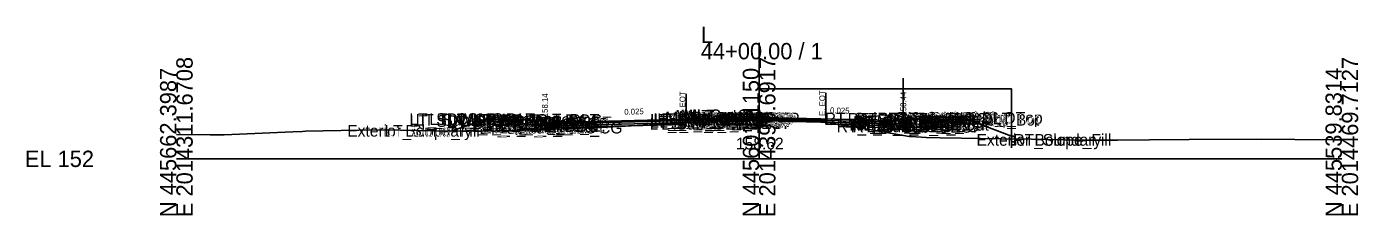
# Model space of a CAD drawing. Extents: x -26 to 4203, y -10 to 9526.
# Drawn here: x 2974.3 to 3202.8, y 3990.3 to 4022.7 of the extents above; entities that cross this region are included whole.
import ezdxf

# ---------------------------------------------------------------- set-up
doc = ezdxf.new("R2010")
doc.units = 0
for name, color, linetype in [('Default', 7, 'Continuous'), ('Exist CMT Pavement', 7, 'Continuous'), ('Exist Cross Section Cell', 7, 'Continuous'), ('Exist XS Center Line Elevation Label', 7, 'Continuous'), ('Exist XS Ground Line', 7, 'Continuous'), ('Prop CMT Conc Surface', 7, 'Continuous'), ('Prop CMT Concrete Structures', 7, 'Continuous'), ('Prop CMT Pvmt Course 1', 7, 'Continuous'), ('Prop CMT Pvmt Course 1 CG', 7, 'Continuous'), ('Prop CMT Pvmt Course 1 Wedge', 7, 'Continuous'), ('Prop CMT Pvmt Course 2', 7, 'Continuous'), ('Prop CMT Pvmt Course 2 Wedge', 7, 'Continuous'), ('Prop CMT Pvmt Course 3', 7, 'Continuous'), ('Prop CMT Pvmt Course 3 Wedge', 7, 'Continuous'), ('Prop CMT Pvmt Surface', 7, 'Continuous'), ('Prop CMT Pvmt Wedge Surface 1', 7, 'Continuous'), ('Prop CMT Pvmt Wedge Surface 2', 7, 'Continuous'), ('Prop CMT Pvmt Wedge Surface 3', 7, 'Continuous'), ('Prop CMT Slope Grass', 7, 'Continuous'), ('Prop CMT Subgrade Earthwork', 7, 'Continuous'), ('Prop XS Finish Grade CurbGutter', 7, 'Continuous'), ('Prop XS Hydro Elevations', 7, 'Continuous'), ('Prop XS Label Text', 7, 'Continuous'), ('Prop XS SE Text', 7, 'Continuous'), ('Prop XS Side Slope Text', 7, 'Continuous'), ('Scratch_Level_0', 7, 'Continuous'), ('Scratch_Level_1', 7, 'Continuous')]:
    doc.layers.add(name, color=color, linetype=linetype)

msp = doc.modelspace()

# ---------------------------------------------------------------- linework, layer by layer
at = {"layer": 'Exist CMT Pavement'}
for p, q in [((3087.46, 4006.16), (3088.82, 4006.26)), ((3088.82, 4006.26), (3095.41, 4006.5)), ((3095.41, 4006.5), (3099.53, 4006.62)), ((3099.53, 4006.62), (3101.77, 4006.61)), ((3101.77, 4006.61), (3105.24, 4006.59)), ((3105.24, 4006.59), (3107.95, 4006.54)), ((3107.95, 4006.54), (3109.82, 4006.51)), ((3109.82, 4006.51), (3110.85, 4006.45)), ((3110.85, 4006.45), (3111.44, 4006.33))]:
    msp.add_line(p, q, dxfattribs=at)
at = {"layer": 'Exist Cross Section Cell'}
for p, q in [((3100, 4000), (3100, 4019.87)), ((3000, 4000), (3100, 4000)), ((3100, 4000), (3200, 4000))]:
    msp.add_line(p, q, dxfattribs=at)
at = {"layer": 'Exist XS Ground Line'}
msp.add_lwpolyline([(3000, 4004.16), (3005.82, 4004.13), (3008.23, 4004.14), (3020.01, 4004.65), (3021.66, 4004.71), (3022.14, 4004.73), (3034.32, 4004.98), (3038.46, 4004.94), (3046.97, 4004.77), (3054.78, 4004.79), (3057.51, 4004.82), (3059.63, 4004.92), (3071.1, 4005.31), (3071.77, 4005.32), (3072.75, 4005.36), (3073.88, 4005.42), (3087.44, 4006.15), (3088.28, 4006.22), (3088.82, 4006.26), (3089.16, 4006.27), (3089.55, 4006.29), (3092.22, 4006.4), (3092.78, 4006.42), (3093.52, 4006.45), (3094.59, 4006.48), (3095.41, 4006.5), (3097.66, 4006.57), (3098.53, 4006.6), (3099.53, 4006.62), (3100, 4006.62), (3101.77, 4006.61), (3104.86, 4006.59), (3105.24, 4006.59), (3105.74, 4006.58), (3107.01, 4006.55), (3107.95, 4006.54), (3109.82, 4006.51), (3110.85, 4006.45), (3111.46, 4006.33), (3113.17, 4005.96), (3113.8, 4005.83), (3114.41, 4005.73), (3116.66, 4005.44), (3125.77, 4003.86), (3126.08, 4003.83), (3128.66, 4003.66), (3131.06, 4003.58), (3134.68, 4003.55), (3141.39, 4003.42), (3146.72, 4003.35), (3155.35, 4003.22), (3161.53, 4003.21), (3166.98, 4003.27), (3173.81, 4003.3), (3186.3, 4003.4), (3191.94, 4003.32), (3198.59, 4003.27), (3200, 4003.26)], dxfattribs=at)
at = {"layer": 'Prop CMT Conc Surface'}
for points in [[(3058.75, 4006.72), (3053.75, 4006.82)], [(3063.25, 4006.14), (3063.25, 4006.63), (3062.75, 4006.63)], [(3065.25, 4006.26), (3063.25, 4006.14)], [(3122.75, 4006.56), (3124.75, 4006.43)], [(3124.75, 4006.43), (3124.75, 4006.93), (3125.25, 4006.93)], [(3129.25, 4007.02), (3134.25, 4007.12)]]:
    msp.add_lwpolyline(points, dxfattribs=at)
at = {"layer": 'Prop CMT Concrete Structures'}
for points in [[(3053.75, 4006.49), (3053.75, 4006.82)], [(3053.75, 4006.82), (3058.75, 4006.72)], [(3058.75, 4006.39), (3053.75, 4006.49)], [(3058.75, 4006.72), (3058.75, 4006.39)], [(3065.25, 4006.26), (3063.25, 4006.14), (3063.25, 4006.63), (3062.75, 4006.63)], [(3062.75, 4006.63), (3062.75, 4005.62), (3065.25, 4005.68)], [(3065.25, 4005.68), (3065.25, 4006.26)], [(3096, 4007.23), (3095.99, 4007.4), (3095.24, 4007.65), (3094, 4007.67), (3092.76, 4007.35), (3092.01, 4007.1), (3092, 4006.93)], [(3092, 4006.93), (3096, 4007.23)], [(3122.75, 4006.56), (3124.75, 4006.43), (3124.75, 4006.93), (3125.25, 4006.93)], [(3125.25, 4006.93), (3125.25, 4005.92), (3122.75, 4005.98)], [(3122.75, 4005.98), (3122.75, 4006.56)], [(3134.25, 4007.12), (3129.25, 4007.02)], [(3129.25, 4007.02), (3129.25, 4006.69)], [(3129.25, 4006.69), (3134.25, 4006.79)], [(3134.25, 4006.79), (3134.25, 4007.12)]]:
    msp.add_lwpolyline(points, dxfattribs=at)
at = {"layer": 'Prop CMT Pvmt Course 1'}
for points in [[(3092, 4006.93), (3065.25, 4006.26)], [(3065.25, 4006.01), (3087.44, 4006.57)], [(3065.25, 4006.26), (3065.25, 4006.01)], [(3087.44, 4006.69), (3092, 4006.81)], [(3087.44, 4006.57), (3087.44, 4006.69)], [(3092, 4006.93), (3096, 4007.23)], [(3096, 4006.98), (3092, 4006.68)], [(3092, 4006.68), (3092, 4006.93)], [(3092, 4006.68), (3092, 4006.93)], [(3092, 4006.81), (3092, 4006.68), (3092, 4006.68)], [(3096, 4007.23), (3096, 4006.98)], [(3096, 4007.23), (3122.75, 4006.56)], [(3096, 4006.98), (3096, 4007.23)], [(3111.46, 4006.72), (3096, 4007.11)], [(3096, 4007.11), (3096, 4006.98), (3096, 4006.98)], [(3111.46, 4006.6), (3111.46, 4006.72)], [(3122.75, 4006.31), (3111.46, 4006.6)], [(3122.75, 4006.56), (3122.75, 4006.31)]]:
    msp.add_lwpolyline(points, dxfattribs=at)
at = {"layer": 'Prop CMT Pvmt Course 1 CG'}
for points in [[(3065.25, 4005.68), (3062.25, 4005.61), (3061.91, 4005.26)], [(3061.91, 4005.26), (3065.25, 4005.35)], [(3065.25, 4005.35), (3065.25, 4005.68)], [(3122.75, 4005.98), (3125.75, 4005.91), (3126.09, 4005.56)], [(3122.75, 4005.65), (3122.75, 4005.98)], [(3126.09, 4005.56), (3122.75, 4005.65)]]:
    msp.add_lwpolyline(points, dxfattribs=at)
at = {"layer": 'Prop CMT Pvmt Course 1 Wedge'}
for points in [[(3087.44, 4006.69), (3087.44, 4006.69), (3087.63, 4006.7), (3088.28, 4006.72), (3088.82, 4006.73), (3089.16, 4006.74), (3089.55, 4006.75), (3092, 4006.81)], [(3087.44, 4006.57), (3087.44, 4006.69)], [(3092, 4006.68), (3089.55, 4006.62), (3089.16, 4006.61), (3088.82, 4006.6), (3088.28, 4006.59), (3087.63, 4006.57), (3087.44, 4006.57), (3087.44, 4006.57)], [(3092, 4006.81), (3092, 4006.68)], [(3096, 4007.11), (3097.66, 4007.07), (3098.53, 4007.04), (3099.53, 4007.02), (3101.38, 4006.97), (3101.64, 4006.97), (3101.77, 4006.96), (3104.86, 4006.89), (3105.24, 4006.88), (3105.74, 4006.86), (3107.01, 4006.83), (3107.95, 4006.81), (3109.82, 4006.76), (3110.85, 4006.74), (3111.46, 4006.72), (3111.46, 4006.72)], [(3096, 4006.98), (3096, 4007.11)], [(3111.46, 4006.6), (3111.46, 4006.6), (3110.85, 4006.61), (3109.82, 4006.64), (3107.95, 4006.68), (3107.01, 4006.71), (3105.74, 4006.74), (3105.24, 4006.75), (3104.86, 4006.76), (3101.77, 4006.84), (3101.64, 4006.84), (3101.38, 4006.85), (3099.53, 4006.89), (3098.53, 4006.92), (3097.66, 4006.94), (3096, 4006.98)], [(3111.46, 4006.72), (3111.46, 4006.6)]]:
    msp.add_lwpolyline(points, dxfattribs=at)
at = {"layer": 'Prop CMT Pvmt Course 2'}
for points in [[(3087.44, 4006.57), (3065.25, 4006.01)], [(3065.25, 4005.68), (3087.44, 4006.24)], [(3087.44, 4006.24), (3087.44, 4006.57)], [(3092, 4006.68), (3096, 4006.98)], [(3092, 4006.35), (3092, 4006.68)], [(3096, 4006.98), (3096, 4006.65)], [(3111.46, 4006.26), (3111.46, 4006.6)], [(3111.46, 4006.6), (3122.75, 4006.31)], [(3122.75, 4005.98), (3111.46, 4006.26)], [(3122.75, 4006.31), (3122.75, 4005.98)], [(3065.25, 4006.01), (3065.25, 4005.68)]]:
    msp.add_lwpolyline(points, dxfattribs=at)
at = {"layer": 'Prop CMT Pvmt Course 2 Wedge'}
for points in [[(3087.44, 4006.57), (3087.44, 4006.57), (3087.63, 4006.57), (3088.28, 4006.59), (3088.82, 4006.6), (3089.16, 4006.61), (3089.55, 4006.62), (3092, 4006.68)], [(3087.44, 4006.24), (3087.44, 4006.57)], [(3092, 4006.39), (3089.74, 4006.29), (3089.55, 4006.29), (3089.16, 4006.28), (3088.82, 4006.27), (3088.28, 4006.26), (3087.63, 4006.24), (3087.44, 4006.24), (3087.44, 4006.24)], [(3092, 4006.68), (3092, 4006.39)], [(3096, 4006.98), (3097.66, 4006.94), (3098.53, 4006.92), (3099.53, 4006.89), (3101.38, 4006.85), (3101.64, 4006.84), (3101.77, 4006.84), (3104.86, 4006.76), (3105.24, 4006.75), (3105.74, 4006.74), (3107.01, 4006.71), (3107.95, 4006.68), (3109.82, 4006.64), (3110.85, 4006.61), (3111.46, 4006.6), (3111.46, 4006.6)], [(3096, 4006.65), (3096, 4006.98)], [(3111.46, 4006.33), (3111.46, 4006.33), (3110.85, 4006.45), (3109.82, 4006.51), (3107.95, 4006.54), (3107.01, 4006.55), (3105.74, 4006.58), (3105.24, 4006.59), (3104.86, 4006.59), (3101.77, 4006.61), (3101.64, 4006.61), (3101.38, 4006.62), (3099.53, 4006.62), (3098.53, 4006.6), (3098.35, 4006.59), (3097.66, 4006.61), (3096, 4006.65)], [(3111.46, 4006.6), (3111.46, 4006.33)]]:
    msp.add_lwpolyline(points, dxfattribs=at)
at = {"layer": 'Prop CMT Pvmt Course 3'}
for points in [[(3087.44, 4006.24), (3065.25, 4005.68)], [(3087.44, 4005.9), (3087.44, 4006.24)], [(3111.46, 4006.26), (3122.75, 4005.98)], [(3111.46, 4005.93), (3111.46, 4006.26)], [(3065.25, 4005.35), (3087.44, 4005.9)], [(3065.25, 4005.68), (3065.25, 4005.35)], [(3122.75, 4005.65), (3111.46, 4005.93)], [(3122.75, 4005.98), (3122.75, 4005.65)]]:
    msp.add_lwpolyline(points, dxfattribs=at)
at = {"layer": 'Prop CMT Pvmt Course 3 Wedge'}
for points in [[(3087.44, 4006.24), (3087.44, 4006.24), (3087.63, 4006.24), (3088.28, 4006.26), (3088.82, 4006.27), (3089.16, 4006.28), (3089.55, 4006.29), (3089.76, 4006.29)], [(3089.76, 4006.29), (3089.55, 4006.29), (3089.16, 4006.27), (3088.82, 4006.26), (3088.28, 4006.22), (3087.63, 4006.18), (3087.44, 4006.15), (3087.44, 4006.15)], [(3087.44, 4006.15), (3087.44, 4006.24)], [(3096, 4006.65), (3097.66, 4006.61), (3098.36, 4006.59)], [(3098.36, 4006.59), (3097.66, 4006.57), (3096, 4006.52)]]:
    msp.add_lwpolyline(points, dxfattribs=at)
at = {"layer": 'Prop CMT Pvmt Surface'}
for points in [[(3092, 4006.93), (3065.25, 4006.26)], [(3092, 4006.93), (3096, 4007.23)], [(3096, 4007.23), (3122.75, 4006.56)]]:
    msp.add_lwpolyline(points, dxfattribs=at)
at = {"layer": 'Prop CMT Pvmt Wedge Surface 1'}
for points in [[(3087.44, 4006.57), (3065.25, 4006.01)], [(3065.25, 4006.01), (3065.25, 4006.26)], [(3092, 4006.81), (3087.44, 4006.69)], [(3087.44, 4006.69), (3087.44, 4006.57)], [(3092, 4006.93), (3092, 4006.68), (3092, 4006.68), (3092, 4006.81)], [(3096, 4007.23), (3096, 4006.98), (3096, 4006.98), (3096, 4007.11)], [(3096, 4007.11), (3111.46, 4006.72)], [(3111.46, 4006.72), (3111.46, 4006.6)], [(3111.46, 4006.6), (3122.75, 4006.31)], [(3122.75, 4006.31), (3122.75, 4006.56)]]:
    msp.add_lwpolyline(points, dxfattribs=at)
at = {"layer": 'Prop CMT Pvmt Wedge Surface 2'}
for points in [[(3092, 4006.68), (3065.25, 4006.01)], [(3065.25, 4006.01), (3065.25, 4006.26)], [(3092, 4006.93), (3092, 4006.68)], [(3096, 4007.23), (3096, 4006.98)], [(3096, 4006.98), (3122.75, 4006.31)], [(3122.75, 4006.31), (3122.75, 4006.56)]]:
    msp.add_lwpolyline(points, dxfattribs=at)
at = {"layer": 'Prop CMT Pvmt Wedge Surface 3'}
for points in [[(3092, 4006.35), (3065.25, 4005.68)], [(3065.25, 4005.68), (3065.25, 4006.26)], [(3092, 4006.93), (3092, 4006.35)], [(3096, 4006.65), (3092, 4006.35)], [(3096, 4007.23), (3096, 4006.65)], [(3096, 4006.65), (3122.75, 4005.98)], [(3122.75, 4005.98), (3122.75, 4006.56)]]:
    msp.add_lwpolyline(points, dxfattribs=at)
at = {"layer": 'Prop CMT Slope Grass'}
msp.add_line((3134.75, 4007.12), (3143.33, 4003.89), dxfattribs=at)
for points in [[(3053.25, 4006.82), (3047.09, 4004.77)], [(3062.75, 4006.63), (3053.25, 4006.82)], [(3125.25, 4006.93), (3134.75, 4007.12)], [(3143.33, 4003.89), (3143.33, 4002.39), (3144, 4002.39), (3144, 4003.39)]]:
    msp.add_lwpolyline(points, dxfattribs=at)
at = {"layer": 'Prop CMT Subgrade Earthwork'}
for points in [[(3065.25, 4005.35), (3061.91, 4005.26), (3060.49, 4006.68)], [(3111.46, 4005.93), (3111.44, 4006.33)], [(3122.75, 4005.65), (3126.09, 4005.56), (3127.51, 4006.98)], [(3087.44, 4005.9), (3065.25, 4005.35)], [(3087.44, 4005.9), (3087.46, 4006.16)], [(3111.46, 4005.93), (3122.75, 4005.65)]]:
    msp.add_lwpolyline(points, dxfattribs=at)
at = {"layer": 'Prop XS Finish Grade CurbGutter'}
for p, q in [((3143.33, 4003.89), (3143.52, 4003.89)), ((3143.33, 4003.89), (3144, 4003.89)), ((3143.33, 4003.89), (3143.33, 4002.89)), ((3143.33, 4002.89), (3143.33, 4002.39)), ((3143.33, 4002.89), (3144, 4002.89)), ((3143.33, 4002.39), (3144, 4002.39)), ((3144, 4003.47), (3143.64, 4003.83)), ((3144, 4003.47), (3144, 4002.89)), ((3144, 4003.39), (3144, 4003.39)), ((3144, 4002.89), (3144, 4002.39))]:
    msp.add_line(p, q, dxfattribs=at)
msp.add_arc((3143.52, 4003.72), 0.166, 43.9997, 90, dxfattribs=at)
at = {"layer": 'Prop XS Label Text'}
for p, q in [((3087.46, 4011.16), (3087.46, 4006.16)), ((3111.44, 4011.33), (3111.44, 4006.33))]:
    msp.add_line(p, q, dxfattribs=at)
at = {"layer": 'Scratch_Level_1'}
msp.add_line((3124.75, 4006.93), (3124.75, 4013.86), dxfattribs=at)
msp.add_lwpolyline([(3100, 4012), (3143.33, 4012), (3143.33, 4001.87)], dxfattribs=at)

# ---------------------------------------------------------------- texts
at = {"layer": 'Default'}
msp.add_text('-', height=0.0001, dxfattribs=at).set_placement((3000, 4000))
at = {"layer": 'Exist Cross Section Cell'}
for s, p in [('L', (3090, 4019.87)), ('44+00.00 / 1', (3090, 4017.07)), ('EL 152', (2974, 3998.6))]:
    msp.add_text(s, height=2.8, dxfattribs=at).set_placement(p)
for s, p in [('N 445662.3987', (3000, 3990)), ('E 2014311.6708', (3002.8, 3990)), ('N 445601.1150', (3100, 3990)), ('E 2014390.6917', (3102.8, 3990)), ('N 445539.8314', (3200, 3990)), ('E 2014469.7127', (3202.8, 3990))]:
    msp.add_text(s, height=2.8, rotation=90, dxfattribs=at).set_placement(p)
at = {"layer": 'Exist XS Center Line Elevation Label'}
msp.add_text('158.62', height=2, dxfattribs=at).set_placement((3096.03, 4001.62))
at = {"layer": 'Prop XS Hydro Elevations'}
for s, p in [('158.14', (3063.75, 4007.14)), ('158.44', (3125.25, 4007.43))]:
    msp.add_text(s, height=1, rotation=90, dxfattribs=at).set_placement(p)
at = {"layer": 'Prop XS Label Text'}
for p in [(3087.36, 4007.18), (3111.34, 4007.36)]:
    msp.add_text('E. EOT', height=1, rotation=90, dxfattribs=at).set_placement(p)
at = {"layer": 'Prop XS SE Text'}
for rotation, p in [(1.4305, (3076.87, 4007.56)), (358.5691, (3112.17, 4007.83))]:
    msp.add_text('0.025', height=1, rotation=rotation, dxfattribs=at).set_placement(p)
at = {"layer": 'Prop XS Side Slope Text'}
for s, rotation, p in [('3:1', 18.4349, (3048.63, 4005.72)), ('VAR.', 339.32, (3137.4, 4006.63))]:
    msp.add_text(s, height=1, rotation=rotation, dxfattribs=at).set_placement(p)
at = {"layer": 'Scratch_Level_0'}
for s, p in [('MI_Top Out', (3086.47, 4006.45)), ('MI_Crown', (3087.07, 4006.47)), ('LT_SDWK_Out_Top', (3039.99, 4005.82)), ('LT_SDWK_Out_Bot', (3040.02, 4005.49)), ('LT_Sub_Trench_Out_DLT', (3041.06, 4005.68)), ('LT_CSLP_Pnt', (3043.42, 4005.82)), ('LT_SDWK_In_Top', (3046.61, 4005.73)), ('LT_SDWK_In_Bot', (3046.64, 4005.39)), ('LT_CG1_Shelf_Out', (3048.8, 4004.61)), ('LT_CG_Top_Face', (3050.51, 4005.63)), ('LT_CG_Top_BOC', (3051.03, 4005.63)), ('LT_CG_Bot_BOC', (3051.06, 4004.62)), ('LT_CG_Top_Gut', (3051.49, 4005.14)), ('LT_Sub_OEOP', (3052.02, 4004.26)), ('LT_Sub_OEOT_CG', (3052.62, 4004.35)), ('LT_CG_Bot_IE', (3055.16, 4004.68)), ('LT_Sub_OEOT', (3055.33, 4004.35)), ('LT_PV2_OEOT', (3055.42, 4005.01)), ('LT_PV3_OEOT', (3055.42, 4004.68)), ('LT_PV1_OEOT', (3055.99, 4005.26)), ('LT_Sub_OEEOP', (3081.21, 4005.02)), ('LT_PV2_OEEOP', (3081.31, 4005.68)), ('LT_PV3_OEEOP', (3081.31, 4005.35)), ('LT_PV1_OEEOP', (3081.87, 4005.81)), ('LT_PV2_IEEOP', (3081.95, 4005.68)), ('LT_PV1_IEEOP', (3082.52, 4005.81)), ('LT_PV2_PGL1', (3082.88, 4005.68)), ('LT_PV3_PGL1', (3082.88, 4005.35)), ('LT_PV2_PGL', (3083.21, 4005.68)), ('LT_PV4_PGL', (3083.21, 4005.02)), ('LT_PV1_PGL', (3083.78, 4005.93)), ('MI_Face In', (3083.9, 4006.1)), ('RT_Sub_OEEOP', (3085.17, 4005.12)), ('RT_PV2_OEEOP', (3085.26, 4005.78)), ('RT_PV3_OEEOP', (3085.26, 4005.45)), ('MI_Top In', (3085.61, 4006.35)), ('RT_PV1_OEEOP', (3085.83, 4005.91)), ('RT_PV2_IEEOP', (3085.91, 4005.78)), ('MI_Face Out', (3086.26, 4006.2)), ('RT_PV1_IEEOP', (3086.47, 4005.91)), ('RT_PV2_PGL1', (3086.83, 4005.98)), ('RT_PV3_PGL1', (3086.83, 4005.65)), ('RT_PV2_PGL', (3087.17, 4005.78)), ('RT_PV4_PGL', (3087.17, 4005.32)), ('MI_Bot Out', (3087.26, 4006.03)), ('RT_PV1_PGL', (3087.73, 4006.03)), ('RT_Sub_Trench_Out_DLT', (3111.28, 4005.9)), ('RT_Sub_OEOT_CG', (3113.32, 4004.57)), ('RT_CG_Top_Face', (3115.21, 4005.85)), ('RT_CG1_Shelf_Out', (3115.5, 4004.83)), ('RT_CG_Bot_IE', (3115.87, 4004.9)), ('RT_Sub_OEOT', (3116.03, 4004.57)), ('RT_PV2_OEOT', (3116.13, 4005.23)), ('RT_PV3_OEOT', (3116.13, 4004.9)), ('RT_CG_Top_Gut', (3116.19, 4005.35)), ('RT_PV1_OEOT', (3116.69, 4005.48)), ('RT_CG_Top_BOC', (3116.74, 4005.85)), ('RT_CG_Bot_BOC', (3116.77, 4004.84)), ('RT_Sub_OEOP', (3119.41, 4004.48)), ('RT_SDWK_In_Top', (3120.31, 4005.94)), ('RT_SDWK_In_Bot', (3120.34, 4005.61)), ('RT_SDWK_Out_Top', (3123.69, 4006.04)), ('RT_SDWK_Out_Bot', (3123.72, 4005.71)), ('RT_Shld_O', (3130.04, 4006.03)), ('CSLP_Pnt', (3130.87, 4006.04)), ('Exterior Boundary', (3029.33, 4003.81)), ('LT_Slope_Fill', (3035.71, 4003.81)), ('Exterior Boundary', (3137.31, 4002.25)), ('RT_Slope_Fill', (3143.64, 4002.25))]:
    msp.add_text(s, height=2, dxfattribs=at).set_placement(p)

doc.saveas('drawing.dxf')
